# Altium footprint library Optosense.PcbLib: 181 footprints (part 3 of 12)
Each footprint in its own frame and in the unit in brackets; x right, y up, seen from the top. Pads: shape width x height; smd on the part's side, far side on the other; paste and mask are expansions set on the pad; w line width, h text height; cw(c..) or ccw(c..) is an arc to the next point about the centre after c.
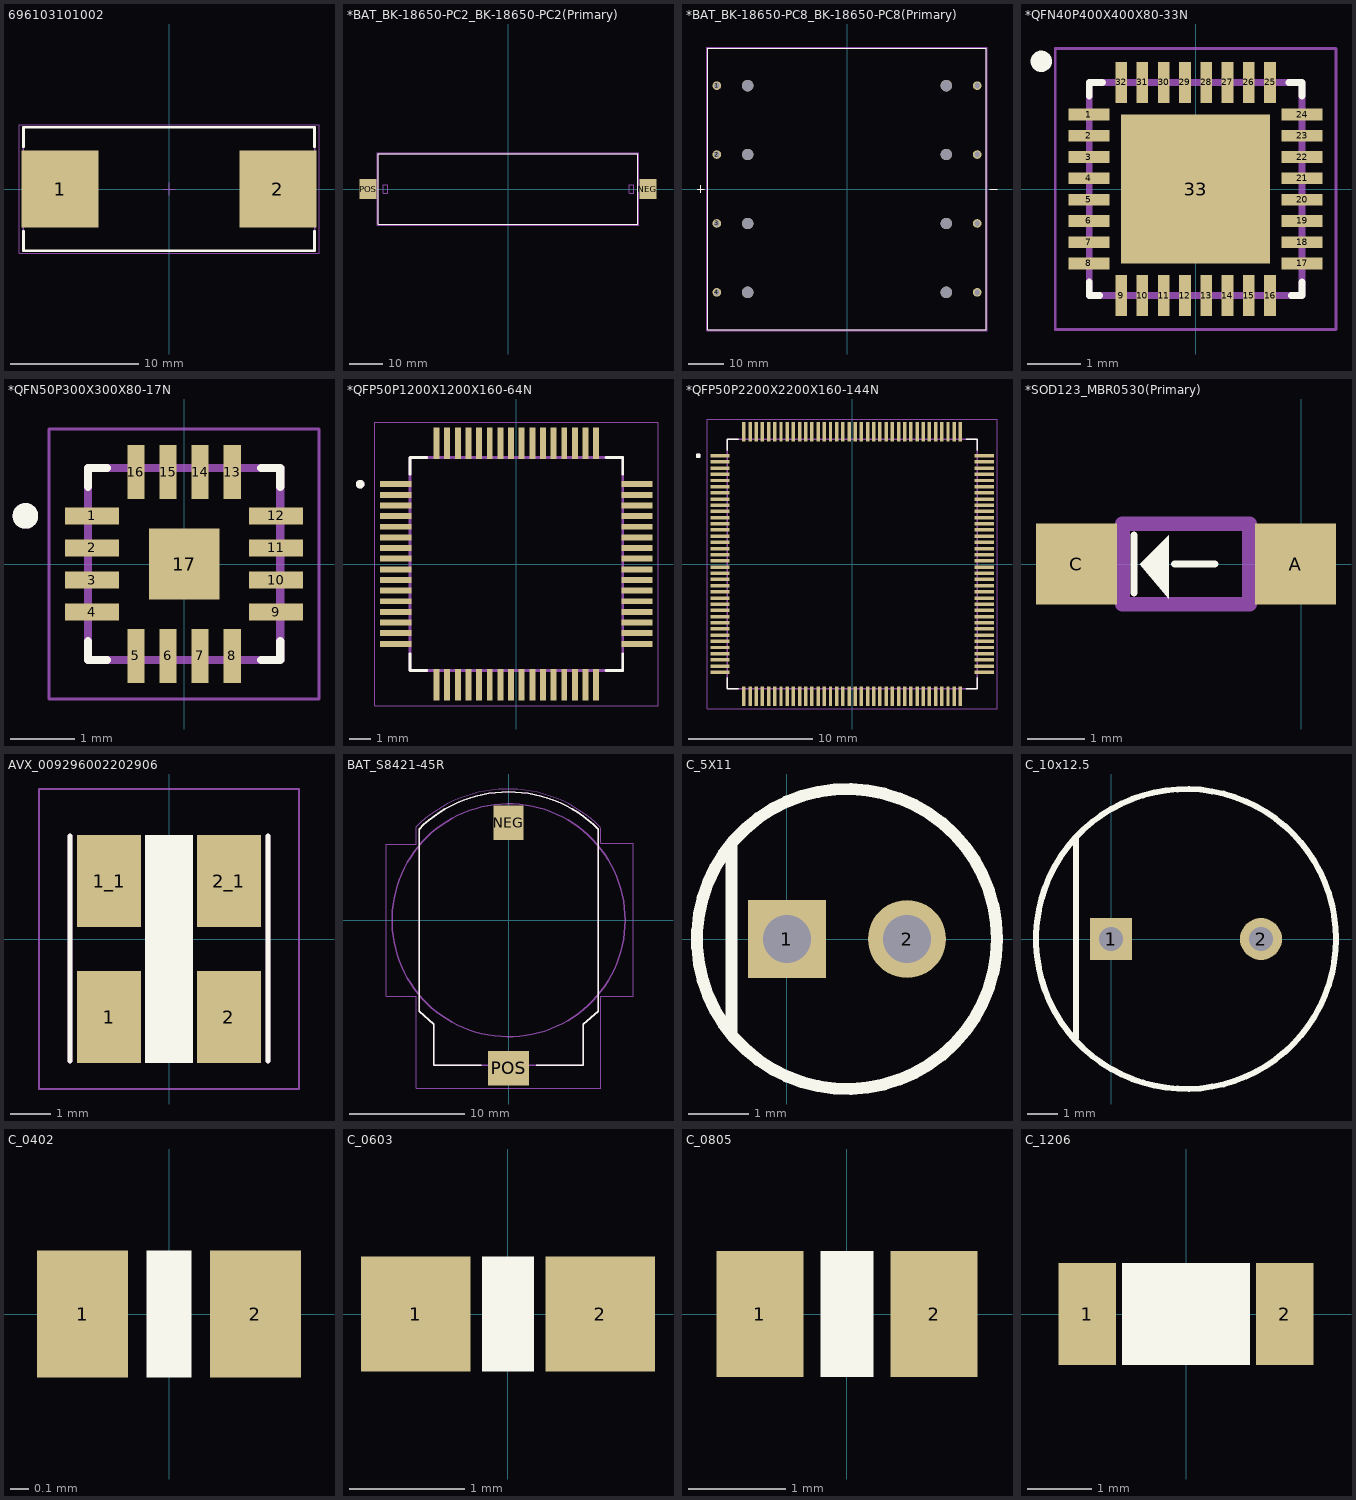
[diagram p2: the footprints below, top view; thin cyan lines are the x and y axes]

## 696103101002 [mm] "FUSEHOLDER BLOCKS - PCB - CLIP COVER - SMT"
height 13.1
pads (2):
  rect 6x6 smd: 1(-8.5,0) 2(8.5,0)
Top Overlay:
  lines w0.2: -11.35,-3.3 -11.35,-4.8 11.35,-4.8 11.35,-3.3 ; -11.35,3.3 -11.35,4.8 11.35,4.8 11.35,3.3
Mechanical 11:
  lines w0.1: -11.35,-4.8 11.35,-4.8 11.35,4.8 -11.35,4.8 -11.35,-4.8
  text ".Designator" at -1.75,-0.75 h1.5
Mechanical 13:
  lines w0.1: -11.35,-4.8 -11.35,4.8 11.35,4.8 11.35,-4.8 -11.35,-4.8
Mechanical 15:
  lines w0.05: -0.5,0 0.5,0 ; 0,-0.5 0,0.5 ; -11.7,-5 11.7,-5 11.7,5 -11.7,5 -11.7,-5
3D body "696103101002.stp": height 12.05, standoff 0.05, extent -11.35,-4.8 11.35,4.8

## *BAT_BK-18650-PC2_BK-18650-PC2(Primary) [mm]
pads (2):
  rect 5x6 smd: NEG(41.5,0) POS(-41.5,0)
Top Overlay:
  lines w0.127: -41.63,0 -39.63,0 ; -40.63,-1 -40.63,1 ; 39.63,0 41.63,0 ; -38.48,-10.49 -38.48,10.49 38.48,10.49 38.48,-10.49 -38.48,-10.49
Mechanical 1:
  lines w0: -36.99,-1.2 -36.99,1.2 -35.61,1.2 -35.61,-1.2 -36.99,-1.2 ; 35.91,-1.2 35.91,1.2 37.29,1.2 37.29,-1.2 35.91,-1.2
Mechanical 13:
  lines w0.127: -38.48,-10.49 -38.48,10.49 ; -38.48,-10.49 38.48,-10.49 ; -38.48,-10.49 -38.48,10.49 ; -38.48,-10.49 38.48,-10.49 ; -38.48,10.49 38.48,10.49 ; -38.48,10.49 38.48,10.49 ; 38.48,-10.49 38.48,10.49 ; 38.48,-10.49 38.48,10.49 ; -41.63,0 -39.63,0 -41.63,0 ; -40.63,-1 -40.63,1 -40.63,-1 ; 39.63,0 41.63,0 39.63,0
Mechanical 16:
  lines w0.05: -38.73,-10.74 -38.73,10.74 38.73,10.74 38.73,-10.74 -38.73,-10.74
3D body "BK-18650-PC2--3DModel-STEP-56544.STEP": height 21.71, standoff -3, extent -38.48,-10.236 38.48,10.744

## *BAT_BK-18650-PC8_BK-18650-PC8(Primary) [mm]
pads (16):
  round 2.4 hole 1.6: 1(-36.45,28.95) 1-(36.45,28.95) 2(-36.45,9.65) 2-(36.45,9.65) 3(-36.45,-9.65) 3-(36.45,-9.65) 4(-36.45,-28.95) 4-(36.45,-28.95)
  round 3.2 hole 3.2 unplated: None(-27.805,-28.955) None(-27.805,-9.65) None(-27.805,9.65) None(-27.805,28.955) None(27.805,-28.955) None(27.805,-9.65) None(27.805,9.65) None(27.805,28.955)
Top Overlay:
  lines w0.127: -42,0 -40,0 ; -41,-1 -41,1 ; 40,0 42,0 ; -38.99,-39.42 38.99,-39.42 38.99,39.42 -38.99,39.42 -38.99,-39.42
Mechanical 13:
  lines w0.127: -38.99,-39.42 38.99,-39.42 ; -38.99,-39.42 -38.99,39.42 ; -38.99,-39.42 38.99,-39.42 ; -38.99,-39.42 -38.99,39.42 ; -38.99,39.42 38.99,39.42 ; -38.99,39.42 38.99,39.42 ; 38.99,-39.42 38.99,39.42 ; 38.99,-39.42 38.99,39.42 ; -42,0 -40,0 -42,0 ; -41,-1 -41,1 -41,-1 ; 40,0 42,0 40,0
Mechanical 16:
  lines w0.05: -39.24,-39.67 39.24,-39.67 39.24,39.67 -39.24,39.67 -39.24,-39.67
3D body "BK-18650-PC8.STEP": height 21.74, standoff -3, extent -39.038,-39.361 38.942,39.479

## *QFN40P400X400X80-33N [mm]
pads (33):
  rect 0.77x0.22 smd: 1(-2.005,1.4) 2(-2.005,1) 3(-2.005,0.6) 4(-2.005,0.2) 5(-2.005,-0.2) 6(-2.005,-0.6) 7(-2.005,-1) 8(-2.005,-1.4) 17(2.005,-1.4) 18(2.005,-1) 19(2.005,-0.6) 20(2.005,-0.2) 21(2.005,0.2) 22(2.005,0.6) 23(2.005,1) 24(2.005,1.4)
  rect 0.22x0.77 smd: 9(-1.4,-2.005) 10(-1,-2.005) 11(-0.6,-2.005) 12(-0.2,-2.005) 13(0.2,-2.005) 14(0.6,-2.005) 15(1,-2.005) 16(1.4,-2.005) 25(1.4,2.005) 26(1,2.005) 27(0.6,2.005) 28(0.2,2.005) 29(-0.2,2.005) 30(-0.6,2.005) 31(-1,2.005) 32(-1.4,2.005)
  rect 2.8x2.8 smd: 33(0,0)
Top Overlay:
  circle w0.2: c-2.9,2.4 r0.1
  lines w0.127: -2,-1.75 -2,-2 -1.8,-2 ; -2,1.75 -2,2 -1.75,2 ; 1.75,2 2,2 2,1.75 ; 1.8,-2 2,-2 2,-1.75
Top Paste:
  region: 0.135,1.125 1.125,1.125 1.125,0.135 0.135,0.135
  region: -1.125,1.125 -0.135,1.125 -0.135,0.135 -1.125,0.135
  region: -1.125,-0.135 -0.135,-0.135 -0.135,-1.125 -1.125,-1.125
  region: 0.135,-0.135 1.125,-0.135 1.125,-1.125 0.135,-1.125
Mechanical 13:
  lines w0.127: -2,-2 2,-2 ; -2,-2 -2,2 ; -2,-2 2,-2 ; -2,-2 -2,2 ; -2,2 2,2 ; -2,2 2,2 ; 2,-2 2,2 ; 2,-2 2,2
Mechanical 16:
  lines w0.05: -2.64,-2.64 2.64,-2.64 2.64,2.64 -2.64,2.64 -2.64,-2.64

## *QFN50P300X300X80-17N [mm]
pads (17):
  rect 0.84x0.27 smd: 1(-1.435,0.75) 2(-1.435,0.25) 3(-1.435,-0.25) 4(-1.435,-0.75) 9(1.435,-0.75) 10(1.435,-0.25) 11(1.435,0.25) 12(1.435,0.75)
  rect 0.27x0.84 smd: 5(-0.75,-1.435) 6(-0.25,-1.435) 7(0.25,-1.435) 8(0.75,-1.435) 13(0.75,1.435) 14(0.25,1.435) 15(-0.25,1.435) 16(-0.75,1.435)
  rect 1.1x1.1 smd: 17(0,0)
Top Overlay:
  circle w0.2: c-2.475,0.75 r0.1
  lines w0.127: -1.5,-1.205 -1.5,-1.5 -1.205,-1.5 ; -1.5,1.205 -1.5,1.5 -1.205,1.5 ; 1.205,-1.5 1.5,-1.5 1.5,-1.205 ; 1.205,1.5 1.5,1.5 1.5,1.205
Top Paste:
  region: -0.35,0.35 0.35,0.35 0.35,-0.35 -0.35,-0.35
Mechanical 13:
  circle w0.2: c-2.475,0.75 r0.1
  circle w0.2: c-2.475,0.75 r0.1
  lines w0.127: -1.5,-1.5 1.5,-1.5 ; -1.5,-1.5 -1.5,1.5 ; -1.5,-1.5 1.5,-1.5 ; -1.5,-1.5 -1.5,1.5 ; -1.5,1.5 1.5,1.5 ; -1.5,1.5 1.5,1.5 ; 1.5,-1.5 1.5,1.5 ; 1.5,-1.5 1.5,1.5
Mechanical 16:
  lines w0.05: -2.105,-2.105 2.105,-2.105 2.105,2.105 -2.105,2.105 -2.105,-2.105

## *QFP50P1200X1200X160-64N [mm]
pads (64):
  rect 1.47x0.28 smd: 1(-5.67,3.75) 2(-5.67,3.25) 3(-5.67,2.75) 4(-5.67,2.25) 5(-5.67,1.75) 6(-5.67,1.25) 7(-5.67,0.75) 8(-5.67,0.25) 9(-5.67,-0.25) 10(-5.67,-0.75) 11(-5.67,-1.25) 12(-5.67,-1.75) 13(-5.67,-2.25) 14(-5.67,-2.75) 15(-5.67,-3.25) 16(-5.67,-3.75) 33(5.67,-3.75) 34(5.67,-3.25) 35(5.67,-2.75) 36(5.67,-2.25) 37(5.67,-1.75) 38(5.67,-1.25) 39(5.67,-0.75) 40(5.67,-0.25) 41(5.67,0.25) 42(5.67,0.75) 43(5.67,1.25) 44(5.67,1.75) 45(5.67,2.25) 46(5.67,2.75) 47(5.67,3.25) 48(5.67,3.75)
  rect 0.28x1.47 smd: 17(-3.75,-5.67) 18(-3.25,-5.67) 19(-2.75,-5.67) 20(-2.25,-5.67) 21(-1.75,-5.67) 22(-1.25,-5.67) 23(-0.75,-5.67) 24(-0.25,-5.67) 25(0.25,-5.67) 26(0.75,-5.67) 27(1.25,-5.67) 28(1.75,-5.67) 29(2.25,-5.67) 30(2.75,-5.67) 31(3.25,-5.67) 32(3.75,-5.67) 49(3.75,5.67) 50(3.25,5.67) 51(2.75,5.67) 52(2.25,5.67) 53(1.75,5.67) 54(1.25,5.67) 55(0.75,5.67) 56(0.25,5.67) 57(-0.25,5.67) 58(-0.75,5.67) 59(-1.25,5.67) 60(-1.75,5.67) 61(-2.25,5.67) 62(-2.75,5.67) 63(-3.25,5.67) 64(-3.75,5.67)
Top Overlay:
  circle w0.2: c-7.34,3.75 r0.1
  lines w0.127: -5,-4.21 -5,-5 -4.21,-5 ; -5,4.21 -5,5 -4.21,5 ; 4.21,-5 5,-5 5,-4.21 ; 4.21,5 5,5 5,4.21
Mechanical 13:
  circle w0.2: c-7.34,3.75 r0.1
  circle w0.2: c-7.34,3.75 r0.1
  lines w0.127: -5,-5 -5,5 ; -5,-5 5,-5 ; -5,-5 -5,5 ; -5,-5 5,-5 ; -5,5 5,5 ; -5,5 5,5 ; 5,-5 5,5 ; 5,-5 5,5
Mechanical 16:
  lines w0.05: -6.655,-6.655 -6.655,6.655 6.655,6.655 6.655,-6.655 -6.655,-6.655

## *QFP50P2200X2200X160-144N [mm]
pads (144):
  rect 1.56x0.28 smd: 1(-10.68,8.75) 2(-10.68,8.25) 3(-10.68,7.75) 4(-10.68,7.25) 5(-10.68,6.75) 6(-10.68,6.25) 7(-10.68,5.75) 8(-10.68,5.25) 9(-10.68,4.75) 10(-10.68,4.25) 11(-10.68,3.75) 12(-10.68,3.25) 13(-10.68,2.75) 14(-10.68,2.25) 15(-10.68,1.75) 16(-10.68,1.25) 17(-10.68,0.75) 18(-10.68,0.25) 19(-10.68,-0.25) 20(-10.68,-0.75) 21(-10.68,-1.25) 22(-10.68,-1.75) 23(-10.68,-2.25) 24(-10.68,-2.75) 25(-10.68,-3.25) 26(-10.68,-3.75) 27(-10.68,-4.25) 28(-10.68,-4.75) 29(-10.68,-5.25) 30(-10.68,-5.75) 31(-10.68,-6.25) 32(-10.68,-6.75) 33(-10.68,-7.25) 34(-10.68,-7.75) 35(-10.68,-8.25) 36(-10.68,-8.75) 73(10.68,-8.75) 74(10.68,-8.25) 75(10.68,-7.75) 76(10.68,-7.25) 77(10.68,-6.75) 78(10.68,-6.25) 79(10.68,-5.75) 80(10.68,-5.25) 81(10.68,-4.75) 82(10.68,-4.25) 83(10.68,-3.75) 84(10.68,-3.25) 85(10.68,-2.75) 86(10.68,-2.25) 87(10.68,-1.75) 88(10.68,-1.25) 89(10.68,-0.75) 90(10.68,-0.25) 91(10.68,0.25) 92(10.68,0.75) 93(10.68,1.25) 94(10.68,1.75) 95(10.68,2.25) 96(10.68,2.75) 97(10.68,3.25) 98(10.68,3.75) 99(10.68,4.25) 100(10.68,4.75) 101(10.68,5.25) 102(10.68,5.75) 103(10.68,6.25) 104(10.68,6.75) 105(10.68,7.25) 106(10.68,7.75) 107(10.68,8.25) 108(10.68,8.75)
  rect 0.28x1.56 smd: 37(-8.75,-10.68) 38(-8.25,-10.68) 39(-7.75,-10.68) 40(-7.25,-10.68) 41(-6.75,-10.68) 42(-6.25,-10.68) 43(-5.75,-10.68) 44(-5.25,-10.68) 45(-4.75,-10.68) 46(-4.25,-10.68) 47(-3.75,-10.68) 48(-3.25,-10.68) 49(-2.75,-10.68) 50(-2.25,-10.68) 51(-1.75,-10.68) 52(-1.25,-10.68) 53(-0.75,-10.68) 54(-0.25,-10.68) 55(0.25,-10.68) 56(0.75,-10.68) 57(1.25,-10.68) 58(1.75,-10.68) 59(2.25,-10.68) 60(2.75,-10.68) 61(3.25,-10.68) 62(3.75,-10.68) 63(4.25,-10.68) 64(4.75,-10.68) 65(5.25,-10.68) 66(5.75,-10.68) 67(6.25,-10.68) 68(6.75,-10.68) 69(7.25,-10.68) 70(7.75,-10.68) 71(8.25,-10.68) 72(8.75,-10.68) 109(8.75,10.68) 110(8.25,10.68) 111(7.75,10.68) 112(7.25,10.68) 113(6.75,10.68) 114(6.25,10.68) 115(5.75,10.68) 116(5.25,10.68) 117(4.75,10.68) 118(4.25,10.68) 119(3.75,10.68) 120(3.25,10.68) 121(2.75,10.68) 122(2.25,10.68) 123(1.75,10.68) 124(1.25,10.68) 125(0.75,10.68) 126(0.25,10.68) 127(-0.25,10.68) 128(-0.75,10.68) 129(-1.25,10.68) 130(-1.75,10.68) 131(-2.25,10.68) 132(-2.75,10.68) 133(-3.25,10.68) 134(-3.75,10.68) 135(-4.25,10.68) 136(-4.75,10.68) 137(-5.25,10.68) 138(-5.75,10.68) 139(-6.25,10.68) 140(-6.75,10.68) 141(-7.25,10.68) 142(-7.75,10.68) 143(-8.25,10.68) 144(-8.75,10.68)
Top Overlay:
  circle w0.2: c-12.44,8.75 r0.1
  lines w0.127: -10.1,-9.21 -10.1,-10.1 -9.21,-10.1 ; -10.1,9.21 -10.1,10.1 -9.21,10.1 ; 9.21,-10.1 10.1,-10.1 10.1,-9.21 ; 9.21,10.1 10.1,10.1 10.1,9.21
Mechanical 4:
  circle w0.2: c-12.44,8.75 r0.1
  circle w0.2: c-12.44,8.75 r0.1
  lines w0.127: -10.1,-10.1 -10.1,10.1 ; -10.1,-10.1 10.1,-10.1 ; -10.1,-10.1 -10.1,10.1 ; -10.1,-10.1 10.1,-10.1 ; -10.1,10.1 10.1,10.1 ; -10.1,10.1 10.1,10.1 ; 10.1,-10.1 10.1,10.1 ; 10.1,-10.1 10.1,10.1
Mechanical 12:
  lines w0.05: -11.71,-11.71 -11.71,11.71 11.71,11.71 11.71,-11.71 -11.71,-11.71
3D body "STM32H743ZIT6--3DModel-STEP-56544.STEP": height 1.63, standoff 0.03, extent -11,-11 11,11

## *SOD123_MBR0530(Primary) [mm]
pads (2):
  rect 1.4x1.4 smd: A(-0.1,0) C(-3.9,0)
Top Overlay:
  region: -2.8,0 -2.3,0.5 -2.3,-0.6
  lines w0.127: -2.9,-0.5 -2.9,0.5 ; -2.2,0 -1.5,0
Mechanical 12:
  region: -3.95,0.4 -3.2,0.4 -3.2,-0.45 -3.95,-0.45
  region: -0.8,0.4 -0.05,0.4 -0.05,-0.45 -0.8,-0.45
  region: -3.95,0.4 -3.2,0.4 -3.2,-0.45 -3.95,-0.45
  region: -0.8,0.4 -0.05,0.4 -0.05,-0.45 -0.8,-0.45
  lines w0.254: -3.1,-0.7 -0.9,-0.7 ; -3.1,-0.7 -3.1,0.7 ; -3.1,-0.7 -0.9,-0.7 ; -3.1,-0.7 -3.1,0.7 ; -3.1,0.7 -0.9,0.7 ; -3.1,0.7 -0.9,0.7 ; -0.9,-0.7 -0.9,0.7 ; -0.9,-0.7 -0.9,0.7
3D body "MBR0530.stp": height 1.35, standoff 0, extent -3.855,-0.8 -0.145,0.8

## AVX_009296002202906 [mm]
pads (4):
  rect 1.6x2.3 smd: 1(-1.5,-1.95) 1_1(-1.5,1.45) 2(1.5,-1.95) 2_1(1.5,1.45)
Top Overlay:
  rectangle: -0.6,-3.1 0.6,2.6
  lines w0.127: -2.475,-3.05 -2.475,2.575 ; 2.475,-3.05 2.475,2.575
Mechanical 13:
  lines w0.127: -2.475,-3.05 -2.475,2.575 ; 2.475,-3.05 2.475,2.575
Mechanical 15:
  lines w0.05: -3.25,-3.75 -3.25,3.75 3.25,3.75 3.25,-3.75 -3.25,-3.75
3D body: height -0.5, standoff -3.5, extent -3.251,-3.759 3.251,3.759

## BAT_S8421-45R [mm]
pads (2):
  rect 2.6x3 smd: NEG(0,8.5)
  rect 3.6x3 smd: POS(0,-12.9)
Top Overlay:
  lines w0.127: -7.8,7.94 -7.8,-7.94 -6.5,-9.06 -6.5,-12.64 -2.4,-12.64 ; -7.8,7.95 cw(c0,0.15) 7.8,7.95 ; 2.4,-12.64 6.5,-12.64 6.5,-9.06 7.8,-7.94 7.8,7.94
Mechanical 13:
  circle w0.127: c0,0 r10.15
  lines w0.127: -7.8,7.94 -7.8,-7.94 -6.5,-9.06 -6.5,-12.64 6.5,-12.64 6.5,-9.06 7.8,-7.94 7.8,7.94 ; -7.8,7.95 cw(c0,0.15) 7.8,7.95
Mechanical 15:
  lines w0.05: -8.1,8.1 cw(c-0.05,0.05) 8,8.1 ; -8.05,8.15 -8.05,6.6 -10.65,6.6 -10.65,-6.6 -8.05,-6.6 -8.05,-14.65 8.05,-14.65 8.05,-6.6 10.85,-6.6 10.85,6.7 8.05,6.7 8.05,8.05
3D body "s8421-45r.stp": height 5.3, standoff 0, extent -7.85,-13.604 7.85,11.15

## C_5X11 [mm]
pads (2):
  rect 1.3x1.3 hole 0.8: 1(0,0)
  round 1.3 hole 0.8: 2(2,0)
Top Overlay:
  circle w0.2: c1,0 r2.5
  lines w0.2: -0.925,-1.55 -0.925,1.55

## C_10x12.5 [mm]
height 12.5
pads (2):
  rect 1.4x1.4 hole 0.8: 1(0,0)
  round 1.4 hole 0.8: 2(5,0)
Top Overlay:
  circle w0.2: c2.5,0 r5
  lines w0.2: -1.175,-3.3 -1.175,3.375
3D body "User Library-KONDANSATOR.STEP": height 12.2, standoff -3.9, extent -1.535,-4.176 6.665,4.024

## C_0402 [mm]
pads (2):
  rect 0.5x0.7 smd: 1(-0.475,0) 2(0.475,0)
Top Overlay:
  rectangle: -0.125,-0.35 0.125,0.35
3D body "User Library-C0402-1.step": height 0.5, standoff 0, extent -0.498,-0.25 0.498,0.25

## C_0603 [mm]
pads (2):
  rect 0.95x1 smd: 1(-0.8,0) 2(0.8,0)
Top Overlay:
  rectangle: -0.225,-0.5 0.225,0.5
3D body "User Library-0603 SMD Capacitor.step": height 0.3, standoff 0, extent -0.8,-0.4 0.8,0.4

## C_0805 [mm]
height 1.25
pads (2):
  rect 0.9x1.3 smd: 1(-0.9,0) 2(0.9,0)
Top Overlay:
  rectangle: -0.275,-0.65 0.275,0.65
3D body "User Library-0805 SMD Capacitor.step": height 0.78, standoff 0, extent -1,-0.625 1,0.625

## C_1206 [mm]
pads (2):
  rect 0.9x1.6 smd: 1(-1.55,0) 2(1.55,0)
Top Overlay:
  rectangle: -1,-0.8 1,0.8
3D body "User Library-1206 SMD Capacitor.step": height 1, standoff 0, extent -1.6,-0.8 1.6,0.8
